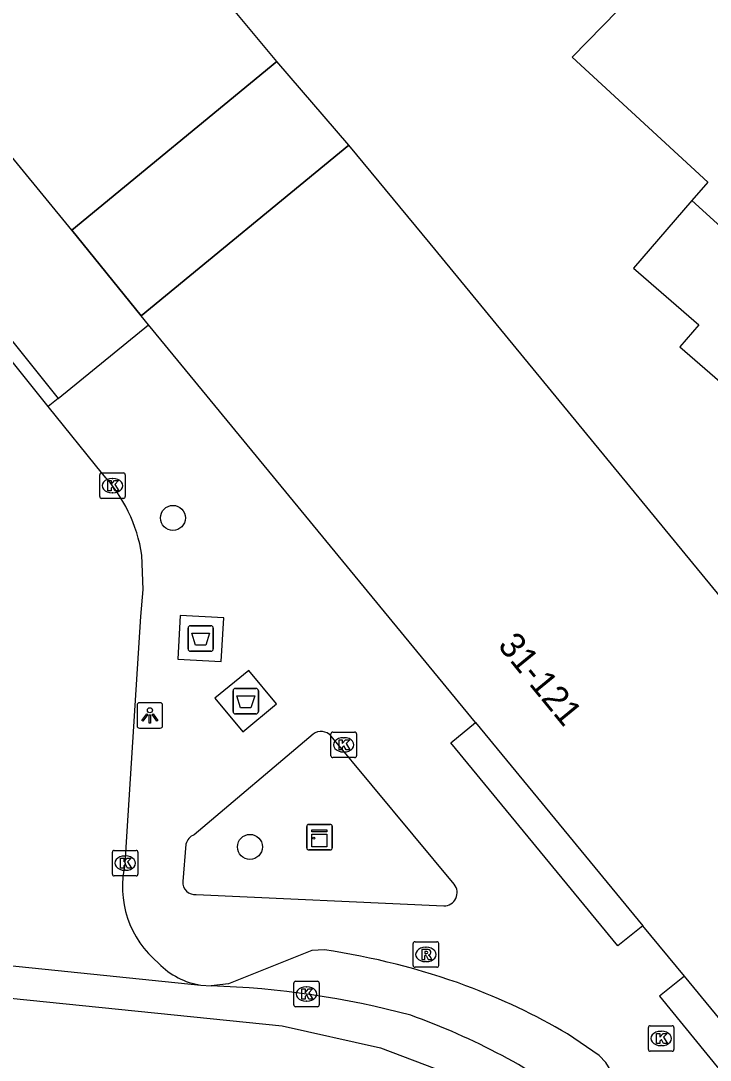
# Model space of a CAD drawing. Extents: x 160664 to 161506, y 382245 to 383288.
# Drawn here: x 160951.59 to 160978.61, y 382930.82 to 382971.53 of the extents above; entities that cross this region are included whole.
import ezdxf

# ---------------------------------------------------------------- set-up
doc = ezdxf.new("R2010")
doc.units = 0
for name, color, linetype in [('IMGEO_Afval_apart_plaats', 7, 'Continuous'), ('IMGEO_Boom', 7, 'Continuous'), ('IMGEO_Kast', 7, 'Continuous'), ('IMGEO_Kolk', 7, 'Continuous'), ('IMGEO_Lichtpunt', 7, 'Continuous'), ('IMGEO_Pand', 7, 'Continuous'), ('IMGEO_Pand_nummerreeks', 7, 'Continuous'), ('IMGEO_Pand_overbouw', 7, 'Continuous'), ('IMGEO_Rijbaan_lokaal_gesloten', 7, 'Continuous'), ('IMGEO_Rijbaan_lokaal_open', 7, 'Continuous'), ('IMGEO_Rioolput', 7, 'Continuous'), ('IMGEO_Voetpad_gesloten', 7, 'Continuous'), ('IMGEO_Voetpad_open', 7, 'Continuous')]:
    doc.layers.add(name, color=color, linetype=linetype)

msp = doc.modelspace()

# ---------------------------------------------------------------- linework, layer by layer
at = {"layer": 'IMGEO_Afval_apart_plaats'}
for p, q in [((160958.144, 382946.94), (160958.144, 382947.74)), ((160958.144, 382947.74), (160958.144, 382946.94)), ((160958.244, 382947.84), (160959.034, 382947.84)), ((160959.034, 382947.84), (160958.244, 382947.84)), ((160959.134, 382947.74), (160959.134, 382946.94)), ((160959.134, 382946.94), (160959.134, 382947.74)), ((160959.034, 382946.84), (160958.244, 382946.84)), ((160958.244, 382946.84), (160959.034, 382946.84)), ((160959.909, 382944.486), (160959.909, 382945.286)), ((160959.909, 382945.286), (160959.909, 382944.486)), ((160960.009, 382945.386), (160960.799, 382945.386)), ((160960.799, 382945.386), (160960.009, 382945.386)), ((160960.899, 382945.286), (160960.899, 382944.486)), ((160960.899, 382944.486), (160960.899, 382945.286)), ((160960.799, 382944.386), (160960.009, 382944.386)), ((160960.009, 382944.386), (160960.799, 382944.386))]:
    msp.add_line(p, q, dxfattribs=at)
for points in [[(160958.287, 382947.554), (160958.991, 382947.554), (160958.842, 382947.084), (160958.436, 382947.084), (160958.287, 382947.554)], [(160960.052, 382945.1), (160960.756, 382945.1), (160960.607, 382944.63), (160960.201, 382944.63), (160960.052, 382945.1)]]:
    msp.add_lwpolyline(points, dxfattribs=at)
for centre, start, end in [((160958.244, 382947.74), 90, 180), ((160958.244, 382947.74), 90, 180), ((160959.034, 382947.74), 0, 90), ((160959.034, 382947.74), 360, 90), ((160958.244, 382946.94), 180, 270), ((160958.244, 382946.94), 180, 270), ((160959.034, 382946.94), 270, 0), ((160959.034, 382946.94), 270, 0), ((160960.009, 382945.286), 90, 180), ((160960.009, 382945.286), 90, 180), ((160960.799, 382945.286), 0, 90), ((160960.799, 382945.286), 360, 90), ((160960.009, 382944.486), 180, 270), ((160960.009, 382944.486), 180, 270), ((160960.799, 382944.486), 270, 0), ((160960.799, 382944.486), 270, 0)]:
    msp.add_arc(centre, 0.1, start, end, dxfattribs=at)
at = {"layer": 'IMGEO_Boom'}
for centre in [(160957.553, 382952.063), (160960.57, 382939.179)]:
    msp.add_circle(centre, 0.489, dxfattribs=at)
at = {"layer": 'IMGEO_Kast'}
for p, q in [((160962.793, 382939.135), (160962.793, 382939.976)), ((160962.793, 382939.976), (160962.793, 382939.135)), ((160962.868, 382940.06), (160963.709, 382940.06)), ((160963.709, 382940.06), (160962.868, 382940.06)), ((160963.793, 382939.985), (160963.793, 382939.144)), ((160963.793, 382939.144), (160963.793, 382939.985)), ((160963.718, 382939.06), (160962.877, 382939.06)), ((160962.877, 382939.06), (160963.718, 382939.06))]:
    msp.add_line(p, q, dxfattribs=at)
for points in [[(160962.988, 382939.85), (160963.588, 382939.85), (160963.588, 382939.765), (160962.988, 382939.765), (160962.988, 382939.85)], [(160962.988, 382939.675), (160963.588, 382939.675), (160963.588, 382939.186), (160962.988, 382939.186), (160962.988, 382939.675)]]:
    msp.add_lwpolyline(points, dxfattribs=at)
msp.add_circle((160963.072, 382939.524), 0.0377, dxfattribs=at)
for centre, start, end in [((160962.871, 382939.982), 92.4484, 184.2845), ((160962.871, 382939.982), 92.4484, 184.2845), ((160963.715, 382939.982), 2.4484, 94.2845), ((160963.715, 382939.982), 2.4484, 94.2845), ((160962.871, 382939.138), 182.4484, 274.2845), ((160962.871, 382939.138), 182.4484, 274.2845), ((160963.715, 382939.138), 272.4484, 4.2845), ((160963.715, 382939.138), 272.4484, 4.2845)]:
    msp.add_arc(centre, 0.0779, start, end, dxfattribs=at)
at = {"layer": 'IMGEO_Kolk'}
for p, q in [((160954.683, 382952.898), (160954.683, 382953.75)), ((160954.758, 382953.824), (160955.61, 382953.824)), ((160955.171, 382953.604), (160955.196, 382953.604)), ((160955.684, 382953.75), (160955.684, 382952.898)), ((160955.61, 382952.824), (160954.758, 382952.824)), ((160955.194, 382953.044), (160955.169, 382953.044)), ((160963.744, 382942.749), (160963.744, 382943.601)), ((160963.819, 382943.675), (160964.671, 382943.675)), ((160964.232, 382943.455), (160964.257, 382943.455)), ((160964.745, 382943.601), (160964.745, 382942.749)), ((160964.671, 382942.675), (160963.819, 382942.675)), ((160964.255, 382942.895), (160964.23, 382942.895)), ((160955.18, 382938.115), (160955.18, 382938.967)), ((160955.255, 382939.041), (160956.107, 382939.041)), ((160956.181, 382938.967), (160956.181, 382938.115)), ((160955.668, 382938.821), (160955.693, 382938.821)), ((160955.691, 382938.261), (160955.666, 382938.261)), ((160956.107, 382938.041), (160955.255, 382938.041)), ((160962.286, 382932.99), (160962.286, 382933.842)), ((160962.361, 382933.916), (160963.213, 382933.916)), ((160962.774, 382933.696), (160962.799, 382933.696)), ((160963.287, 382933.842), (160963.287, 382932.99)), ((160963.213, 382932.916), (160962.361, 382932.916)), ((160962.797, 382933.136), (160962.772, 382933.136)), ((160976.182, 382931.248), (160976.182, 382932.1)), ((160976.257, 382932.174), (160977.109, 382932.174)), ((160977.183, 382932.1), (160977.183, 382931.248)), ((160976.67, 382931.954), (160976.695, 382931.954)), ((160977.109, 382931.174), (160976.257, 382931.174)), ((160976.693, 382931.394), (160976.668, 382931.394))]:
    msp.add_line(p, q, dxfattribs=at)
for points in [[(160954.683, 382952.898), (160954.683, 382953.75)], [(160954.758, 382953.824), (160955.61, 382953.824)], [(160955.684, 382953.75), (160955.684, 382952.898)], [(160955.004, 382953.524), (160955.127, 382953.524), (160955.127, 382953.373), (160955.257, 382953.524), (160955.421, 382953.524), (160955.275, 382953.373), (160955.428, 382953.124), (160955.276, 382953.124), (160955.191, 382953.288), (160955.127, 382953.221), (160955.127, 382953.124), (160955.004, 382953.124), (160955.004, 382953.524)], [(160955.61, 382952.824), (160954.758, 382952.824)], [(160963.744, 382942.749), (160963.744, 382943.601)], [(160963.819, 382943.675), (160964.671, 382943.675)], [(160964.745, 382943.601), (160964.745, 382942.749)], [(160964.065, 382943.375), (160964.188, 382943.375), (160964.188, 382943.224), (160964.318, 382943.375), (160964.482, 382943.375), (160964.336, 382943.224), (160964.489, 382942.975), (160964.337, 382942.975), (160964.252, 382943.139), (160964.188, 382943.072), (160964.188, 382942.975), (160964.065, 382942.975), (160964.065, 382943.375)], [(160964.671, 382942.675), (160963.819, 382942.675)], [(160955.18, 382938.115), (160955.18, 382938.967)], [(160955.255, 382939.041), (160956.107, 382939.041)], [(160956.181, 382938.967), (160956.181, 382938.115)], [(160955.501, 382938.741), (160955.624, 382938.741), (160955.624, 382938.59), (160955.754, 382938.741), (160955.918, 382938.741), (160955.772, 382938.59), (160955.925, 382938.341), (160955.773, 382938.341), (160955.688, 382938.505), (160955.624, 382938.438), (160955.624, 382938.341), (160955.501, 382938.341), (160955.501, 382938.741)], [(160956.107, 382938.041), (160955.255, 382938.041)], [(160962.286, 382932.99), (160962.286, 382933.842)], [(160962.361, 382933.916), (160963.213, 382933.916)], [(160962.607, 382933.616), (160962.73, 382933.616), (160962.73, 382933.465), (160962.86, 382933.616), (160963.024, 382933.616), (160962.878, 382933.465), (160963.031, 382933.216), (160962.879, 382933.216), (160962.794, 382933.38), (160962.73, 382933.313), (160962.73, 382933.216), (160962.607, 382933.216), (160962.607, 382933.616)], [(160963.287, 382933.842), (160963.287, 382932.99)], [(160963.213, 382932.916), (160962.361, 382932.916)], [(160976.182, 382931.248), (160976.182, 382932.1)], [(160976.257, 382932.174), (160977.109, 382932.174)], [(160977.183, 382932.1), (160977.183, 382931.248)], [(160976.503, 382931.874), (160976.626, 382931.874), (160976.626, 382931.723), (160976.756, 382931.874), (160976.92, 382931.874), (160976.774, 382931.723), (160976.927, 382931.474), (160976.775, 382931.474), (160976.69, 382931.638), (160976.626, 382931.571), (160976.626, 382931.474), (160976.503, 382931.474), (160976.503, 382931.874)], [(160977.109, 382931.174), (160976.257, 382931.174)]]:
    msp.add_lwpolyline(points, dxfattribs=at)
for centre, start, end in [((160954.76, 382953.748), 91.552, 178.448), ((160954.76, 382953.748), 91.552, 178.448), ((160955.608, 382953.748), 1.552, 88.448), ((160955.608, 382953.748), 1.552, 88.448), ((160954.76, 382952.9), 181.552, 268.448), ((160954.76, 382952.9), 181.552, 268.448), ((160955.608, 382952.9), 271.552, 358.448), ((160955.608, 382952.9), 271.552, 358.448), ((160963.821, 382943.599), 91.552, 178.448), ((160963.821, 382943.599), 91.552, 178.448), ((160964.669, 382943.599), 1.552, 88.448), ((160964.669, 382943.599), 1.552, 88.448), ((160963.821, 382942.751), 181.552, 268.448), ((160963.821, 382942.751), 181.552, 268.448), ((160964.669, 382942.751), 271.552, 358.448), ((160964.669, 382942.751), 271.552, 358.448), ((160955.257, 382938.965), 91.552, 178.448), ((160955.257, 382938.965), 91.552, 178.448), ((160956.105, 382938.965), 1.552, 88.448), ((160956.105, 382938.965), 1.552, 88.448), ((160955.257, 382938.117), 181.552, 268.448), ((160955.257, 382938.117), 181.552, 268.448), ((160956.105, 382938.117), 271.552, 358.448), ((160956.105, 382938.117), 271.552, 358.448), ((160962.363, 382933.84), 91.552, 178.448), ((160962.363, 382933.84), 91.552, 178.448), ((160963.211, 382933.84), 1.552, 88.448), ((160963.211, 382933.84), 1.552, 88.448), ((160962.363, 382932.992), 181.552, 268.448), ((160962.363, 382932.992), 181.552, 268.448), ((160963.211, 382932.992), 271.552, 358.448), ((160963.211, 382932.992), 271.552, 358.448), ((160976.259, 382932.098), 91.552, 178.448), ((160976.259, 382932.098), 91.552, 178.448), ((160977.107, 382932.098), 1.552, 88.448), ((160977.107, 382932.098), 1.552, 88.448), ((160976.259, 382931.25), 181.552, 268.448), ((160976.259, 382931.25), 181.552, 268.448), ((160977.107, 382931.25), 271.552, 358.448), ((160977.107, 382931.25), 271.552, 358.448)]:
    msp.add_arc(centre, 0.0765, start, end, dxfattribs=at)
for centre, major_axis, ratio, start_param, end_param in [((160955.17, 382953.324), (-0.387, 0.002), 0.722429, 4.712389, 7.853982), ((160955.195, 382953.324), (-0.39, 0.002), 0.717154, 1.570796, 4.712389), ((160964.231, 382943.175), (-0.387, 0.002), 0.722429, 4.712389, 7.853982), ((160964.256, 382943.175), (-0.39, 0.002), 0.717154, 1.570796, 4.712389), ((160955.667, 382938.541), (-0.387, 0.002), 0.722429, 4.712389, 7.853982), ((160955.692, 382938.541), (-0.39, 0.002), 0.717154, 1.570796, 4.712389), ((160962.773, 382933.416), (-0.387, 0.002), 0.722429, 4.712389, 7.853982), ((160962.798, 382933.416), (-0.39, 0.002), 0.717154, 1.570796, 4.712389), ((160976.669, 382931.674), (-0.387, 0.002), 0.722429, 4.712389, 7.853982), ((160976.694, 382931.674), (-0.39, 0.002), 0.717154, 1.570796, 4.712389)]:
    msp.add_ellipse(centre, major_axis=major_axis, ratio=ratio, start_param=start_param, end_param=end_param, dxfattribs=at)
at = {"layer": 'IMGEO_Lichtpunt'}
for p, q in [((160956.15, 382944.729), (160956.15, 382943.922)), ((160956.15, 382944.729), (160956.15, 382943.922)), ((160957.052, 382944.824), (160956.244, 382944.824)), ((160957.052, 382944.824), (160956.244, 382944.824)), ((160957.146, 382943.922), (160957.146, 382944.729)), ((160957.146, 382943.922), (160957.146, 382944.729)), ((160956.244, 382943.828), (160957.052, 382943.828)), ((160956.244, 382943.828), (160957.052, 382943.828))]:
    msp.add_line(p, q, dxfattribs=at)
for points in [[(160956.524, 382944.393), (160956.563, 382944.365), (160956.375, 382944.103), (160956.337, 382944.13), (160956.524, 382944.393)], [(160956.626, 382944.345), (160956.673, 382944.345), (160956.673, 382944.023), (160956.626, 382944.023), (160956.626, 382944.345)], [(160956.736, 382944.365), (160956.774, 382944.392), (160956.961, 382944.13), (160956.922, 382944.102), (160956.736, 382944.365)]]:
    msp.add_lwpolyline(points, dxfattribs=at)
msp.add_circle((160956.649, 382944.527), 0.0994, dxfattribs=at)
for centre, start, end in [((160956.244, 382944.729), 90, 180), ((160956.244, 382944.729), 90, 180), ((160957.052, 382944.729), 0, 90), ((160957.052, 382944.729), 0, 90), ((160956.244, 382943.922), 180, 270), ((160956.244, 382943.922), 180, 270), ((160957.052, 382943.922), 270, 0), ((160957.052, 382943.922), 270, 360)]:
    msp.add_arc(centre, 0.0946, start, end, dxfattribs=at)
at = {"layer": 'IMGEO_Pand'}
for points in [[(160953.589, 382963.329), (160961.617, 382969.937), (160958.423, 382973.784), (160936.91, 383000), (160925.377, 383014.054)], [(160953.589, 382963.329), (160923.54, 383000), (160917.629, 383007.213), (160917.332, 383007.56)], [(160978.78, 382975.821), (160978.583, 382975.62), (160973.196, 382970.113), (160978.517, 382965.213), (160977.888, 382964.488)], [(160999.488, 382938.635), (160995.794, 382942.001), (160986.008, 382950.919), (160980.882, 382946.7), (160967.625, 382962.807), (160964.447, 382966.667), (160956.311, 382959.971)], [(160977.888, 382964.488), (160975.601, 382961.849), (160978.16, 382959.63), (160977.411, 382958.766), (160988.597, 382949.072), (160996.011, 382942.24), (160999.653, 382938.77)], [(160983.622, 382959.281), (160983.601, 382959.296), (160977.888, 382964.488)], [(160956.597, 382959.624), (160956.311, 382959.971)], [(160969.413, 382944.053), (160956.597, 382959.624)], [(160969.413, 382944.053), (160975.966, 382936.092)], [(160977.597, 382934.11), (160975.966, 382936.092)], [(160984.598, 382926.379), (160984.218, 382926.066), (160977.597, 382934.11)]]:
    msp.add_lwpolyline(points, dxfattribs=at)
at = {"layer": 'IMGEO_Pand_overbouw'}
msp.add_lwpolyline([(160961.617, 382969.937), (160953.589, 382963.329), (160956.311, 382959.971), (160964.447, 382966.667)], close=True, dxfattribs=at)
at = {"layer": 'IMGEO_Rijbaan_lokaal_gesloten'}
for points in [[(160874.133, 382934.008), (160885.51, 382936.782), (160890.497, 382938.296), (160895.761, 382938.889), (160961.831, 382932.175), (160965.691, 382931.306), (160969.512, 382929.861), (160972.821, 382927.904), (160976.623, 382925.025), (160978.469, 382923.697)], [(160946.296, 382935.03), (160958.649, 382933.764)], [(160958.649, 382933.764), (160959.055, 382933.734)]]:
    msp.add_lwpolyline(points, dxfattribs=at)
for centre, radius, start, end in [((160957.949, 382899.049), 34.703, 75.1079, 88.1743), ((160957.369, 382906.264), 27.983, 54.1145, 70.1566)]:
    msp.add_arc(centre, radius, start, end, dxfattribs=at)
at = {"layer": 'IMGEO_Rijbaan_lokaal_open'}
for points in [[(160952.666, 382956.429), (160949.045, 382960.931)], [(160954.79, 382953.789), (160952.666, 382956.429)], [(160955.68, 382938.541), (160955.803, 382940.404), (160956.296, 382948.204), (160956.385, 382949.262), (160956.333, 382950.602)]]:
    msp.add_lwpolyline(points, dxfattribs=at)
for centre, radius, start, end in [((160950.43, 382949.711), 5.97, 8.5827, 43.0856), ((160959.466, 382937.627), 3.895, 166.4214, 230.6236), ((160959.063, 382936.6), 2.866, 223.8039, 261.6887)]:
    msp.add_arc(centre, radius, start, end, dxfattribs=at)
at = {"layer": 'IMGEO_Rioolput'}
for p, q in [((160966.963, 382934.538), (160966.963, 382935.39)), ((160967.038, 382935.464), (160967.89, 382935.464)), ((160967.451, 382935.244), (160967.476, 382935.244)), ((160967.964, 382935.39), (160967.964, 382934.538)), ((160967.89, 382934.464), (160967.038, 382934.464)), ((160967.474, 382934.684), (160967.449, 382934.684))]:
    msp.add_line(p, q, dxfattribs=at)
for points in [[(160966.963, 382934.538), (160966.963, 382935.39)], [(160967.038, 382935.464), (160967.89, 382935.464)], [(160967.964, 382935.39), (160967.964, 382934.538)], [(160967.552, 382935.162), (160967.3, 382935.164), (160967.3, 382934.764)], [(160967.3, 382934.764), (160967.424, 382934.764), (160967.424, 382934.926), (160967.435, 382934.926)], [(160967.478, 382935.083), (160967.424, 382935.083), (160967.424, 382935.002)], [(160967.424, 382935.002), (160967.476, 382935.002)], [(160967.482, 382934.897), (160967.553, 382934.764), (160967.693, 382934.764), (160967.628, 382934.89)], [(160967.89, 382934.464), (160967.038, 382934.464)]]:
    msp.add_lwpolyline(points, dxfattribs=at)
for centre, radius, start, end in [((160967.04, 382935.388), 0.0765, 91.552, 178.448), ((160967.04, 382935.388), 0.0765, 91.552, 178.448), ((160967.888, 382935.388), 0.0765, 1.552, 88.448), ((160967.888, 382935.388), 0.0765, 1.552, 88.448), ((160967.434, 382934.873), 0.0533, 26.0293, 88.6989), ((160967.46, 382935.191), 0.19, 274.7715, 282.9687), ((160967.484, 382934.987), 0.0964, 77.0061, 93.1865), ((160967.498, 382935.044), 0.0378, 276.6634, 79.6772), ((160967.551, 382935.052), 0.109, 350.3612, 89.416), ((160967.549, 382935.052), 0.112, 277.5842, 350.9817), ((160967.533, 382934.837), 0.108, 29.5134, 73.7905), ((160967.04, 382934.54), 0.0765, 181.552, 268.448), ((160967.04, 382934.54), 0.0765, 181.552, 268.448), ((160967.888, 382934.54), 0.0765, 271.552, 358.448), ((160967.888, 382934.54), 0.0765, 271.552, 358.448)]:
    msp.add_arc(centre, radius, start, end, dxfattribs=at)
for centre, major_axis, ratio, start_param, end_param in [((160967.45, 382934.964), (-0.387, 0.002), 0.722429, 4.712389, 7.853982), ((160967.475, 382934.964), (-0.39, 0.002), 0.717154, 1.570796, 4.712389)]:
    msp.add_ellipse(centre, major_axis=major_axis, ratio=ratio, start_param=start_param, end_param=end_param, dxfattribs=at)
at = {"layer": 'IMGEO_Voetpad_gesloten'}
for points in [[(160959.543, 382948.146), (160957.838, 382948.241), (160957.739, 382946.53), (160959.438, 382946.441), (160959.543, 382948.146)], [(160960.521, 382946.091), (160959.198, 382944.996), (160960.286, 382943.681), (160961.609, 382944.776), (160960.521, 382946.091)]]:
    msp.add_lwpolyline(points, dxfattribs=at)
at = {"layer": 'IMGEO_Voetpad_open'}
for points in [[(160956.311, 382959.971), (160953.589, 382963.329)], [(160949.045, 382960.931), (160949.433, 382961.245), (160953.054, 382956.743)], [(160953.054, 382956.743), (160956.597, 382959.624)], [(160953.054, 382956.743), (160952.666, 382956.429)], [(160975.966, 382936.092), (160974.981, 382935.303), (160968.435, 382943.251), (160969.413, 382944.053)], [(160963.041, 382943.596), (160958.386, 382939.653)], [(160968.572, 382937.711), (160963.757, 382943.512)], [(160958.059, 382939.286), (160957.934, 382937.816)], [(160958.464, 382937.311), (160968.165, 382936.866)], [(160963.495, 382935.145), (160962.996, 382935.121), (160959.725, 382933.811), (160959.055, 382933.734)], [(160977.597, 382934.11), (160976.611, 382933.329), (160983.105, 382925.384)], [(160977.372, 382926.36), (160976.872, 382926.91), (160974.515, 382930.732), (160974.255, 382931.008), (160973.014, 382931.85)]]:
    msp.add_lwpolyline(points, dxfattribs=at)
for centre, radius, start, end in [((160963.354, 382943.174), 0.526, 40.0265, 126.591), ((160958.57, 382939.16), 0.526, 110.4587, 166.1387), ((160958.419, 382937.794), 0.485, 177.4466, 275.3208), ((160968.165, 382937.387), 0.521, 270.0201, 38.5437), ((160959.237, 382906.713), 28.749, 70.0745, 81.4834), ((160960.292, 382910.213), 25.1, 59.5461, 69.6156)]:
    msp.add_arc(centre, radius, start, end, dxfattribs=at)

# ---------------------------------------------------------------- texts
at = {"layer": 'IMGEO_Pand_nummerreeks'}
msp.add_text('31-121', height=1, rotation=309.2932, dxfattribs=at).set_placement((160970.25, 382947.053))

doc.saveas('drawing.dxf')
